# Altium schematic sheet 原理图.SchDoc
size A2
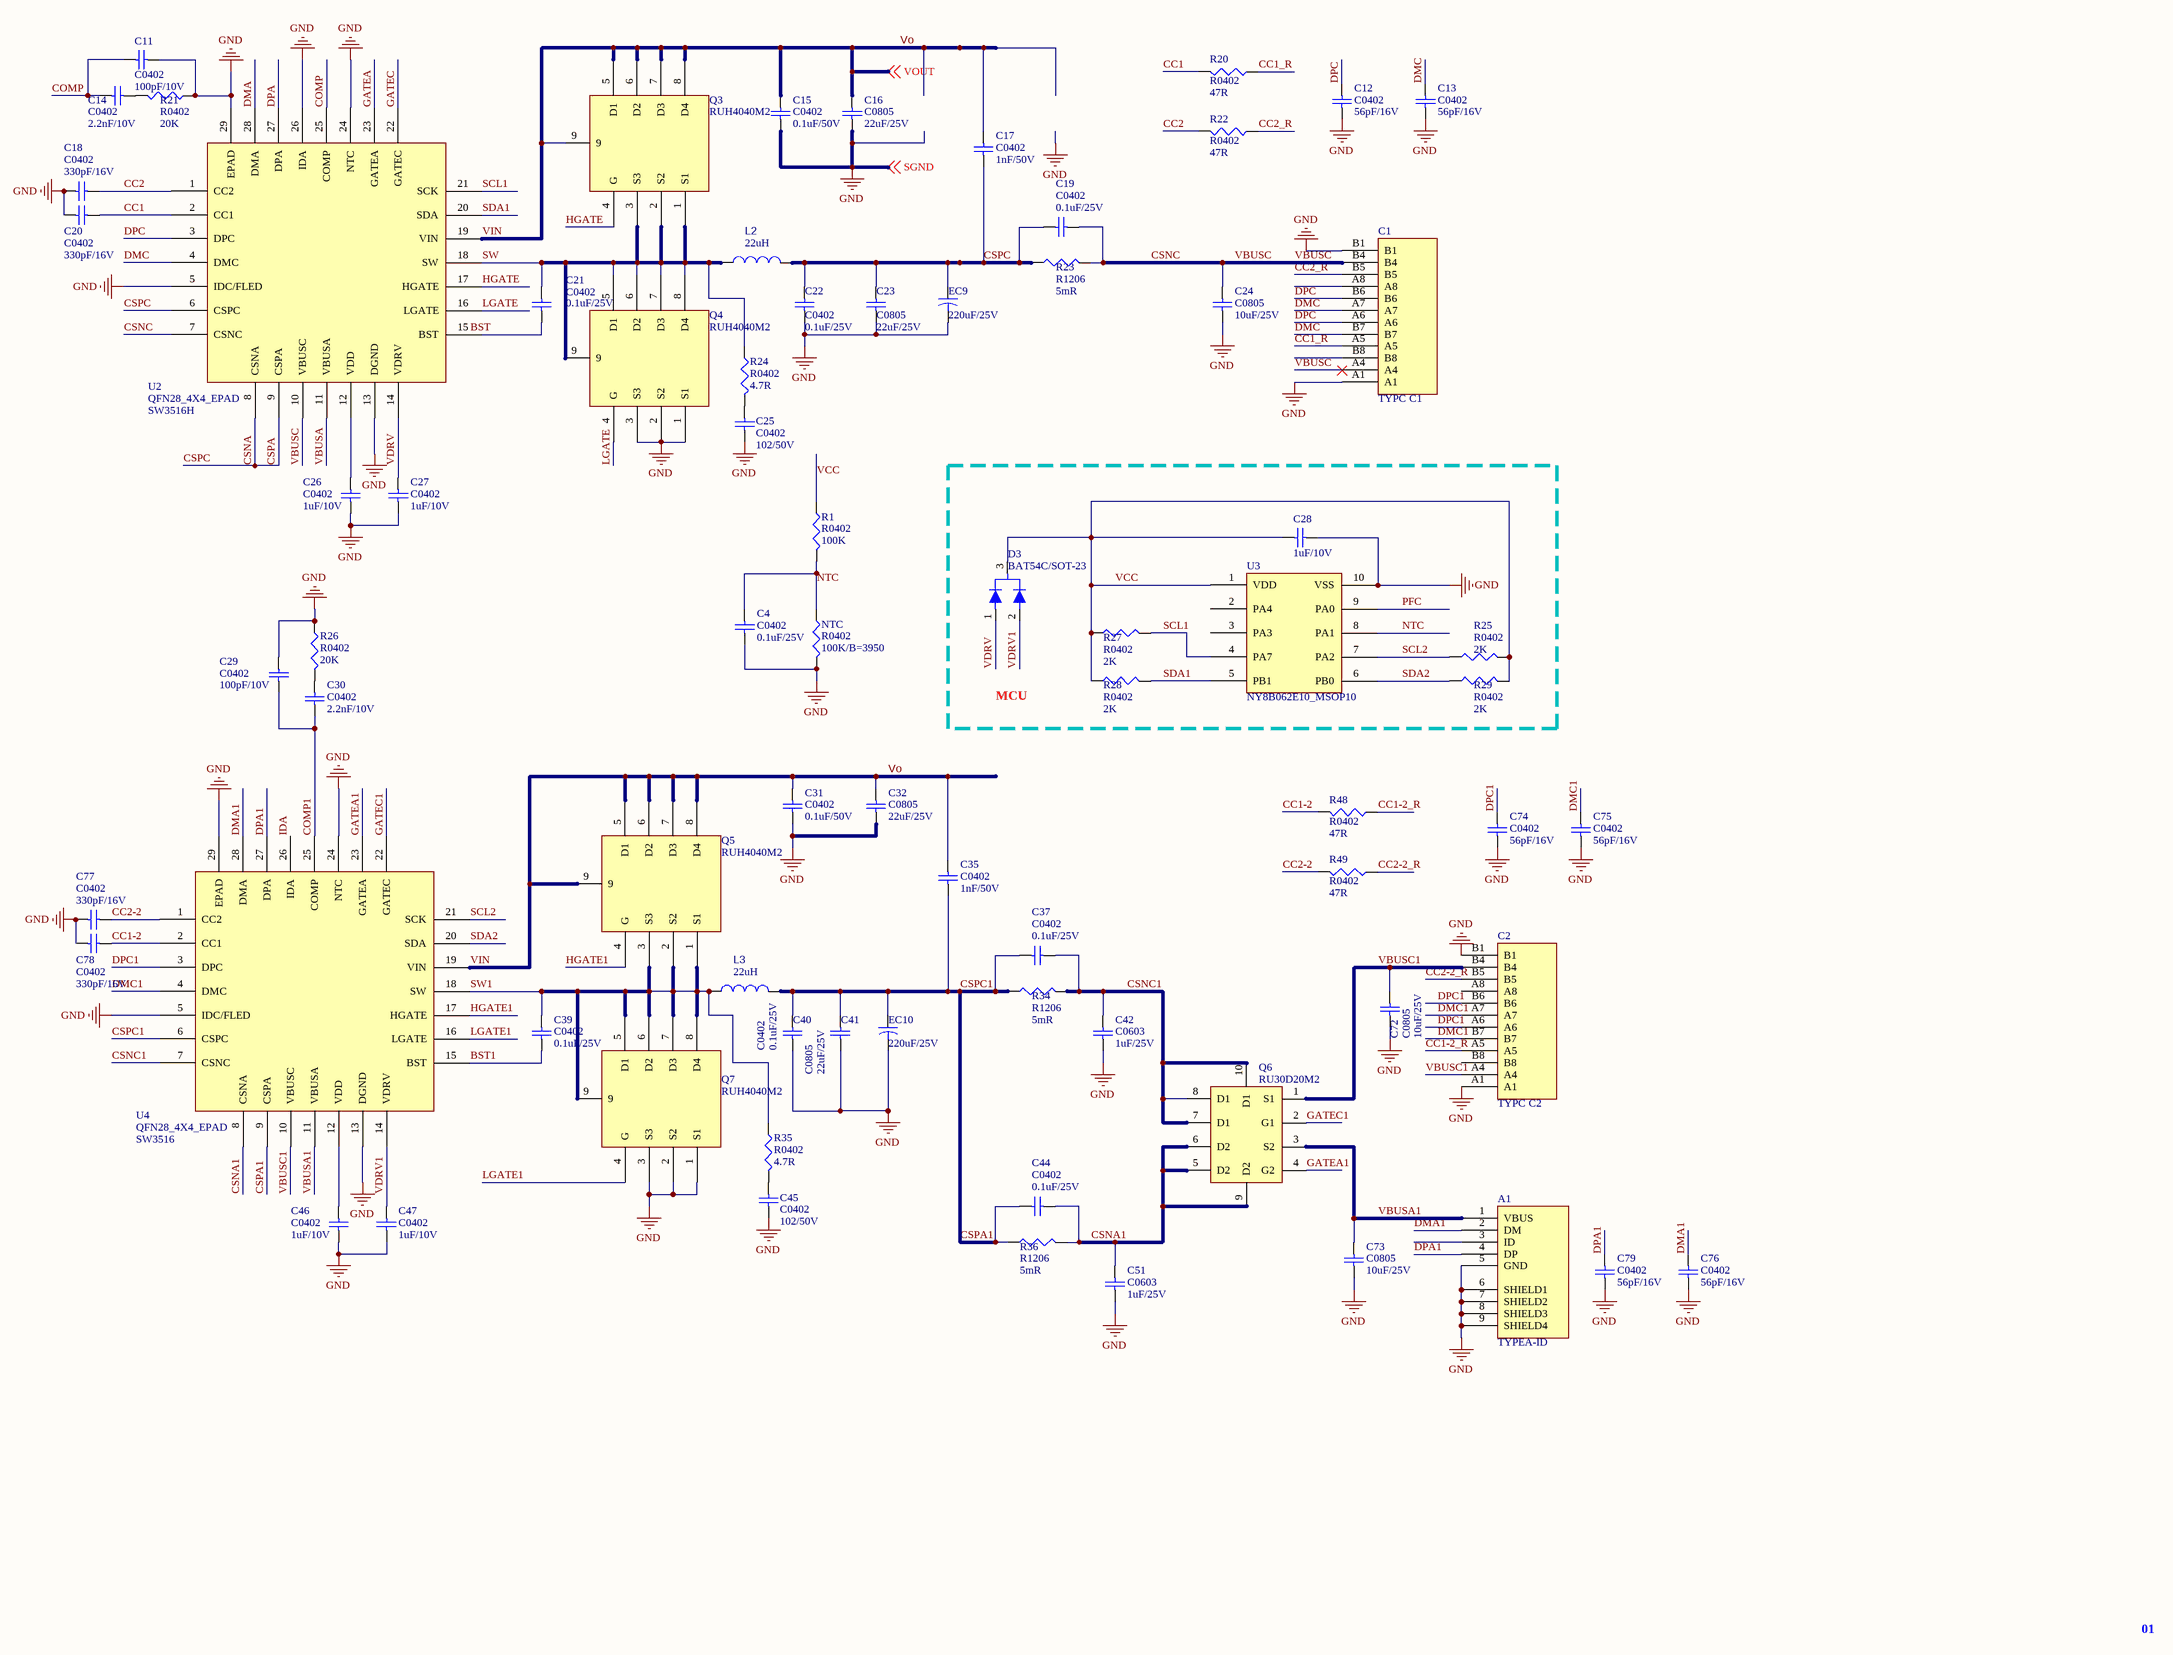
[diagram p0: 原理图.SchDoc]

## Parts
A1  TYPEA-ID  [TYPEA-VOOC]
C1  TYPC C1  [USB C1]
C2  TYPC C2  [USB C1]
C4  C0402  value 0.1uF/25V  [0402C]
C11  C0402  value 100pF/10V  [0402C]
C12  C0402  value 56pF/16V  [0402C]
C13  C0402  value 56pF/16V  [0402C]
C14  C0402  value 2.2nF/10V  [0402C]
C15  C0402  value 0.1uF/50V  [0402C]
C16  C0805  value 22uF/25V  [0805C]
C17  C0402  value 1nF/50V  [0402C]
C18  C0402  value 330pF/16V  [0402C]
C19  C0402  value 0.1uF/25V  [0402C]
C20  C0402  value 330pF/16V  [0402C]
C21  C0402  value 0.1uF/25V  [0402C]
C22  C0402  value 0.1uF/25V  [0402C]
C23  C0805  value 22uF/25V  [0805C]
C24  C0805  value 10uF/25V  [0805C]
C25  C0402  value 102/50V  [0603C]
C26  C0402  value 1uF/10V  [0402C]
C27  C0402  value 1uF/10V  [0402C]
C28  value 1uF/10V  [0402C]  (hidden comment: Cap)
C29  C0402  value 100pF/10V  [0402C]
C30  C0402  value 2.2nF/10V  [0402C]
C31  C0402  value 0.1uF/50V  [0402C]
C32  C0805  value 22uF/25V  [0805C]
C35  C0402  value 1nF/50V  [0402C]
C37  C0402  value 0.1uF/25V  [0402C]
C39  C0402  value 0.1uF/25V  [0402C]
C40  C0402  value 0.1uF/25V  [0402C]
C41  C0805  value 22uF/25V  [0805C]
C42  C0603  value 1uF/25V  [0603C]
C44  C0402  value 0.1uF/25V  [0402C]
C45  C0402  value 102/50V  [0603C]
C46  C0402  value 1uF/10V  [0402C]
C47  C0402  value 1uF/10V  [0402C]
C51  C0603  value 1uF/25V  [0603C]
C72  C0805  value 10uF/25V  [0805C]
C73  C0805  value 10uF/25V  [0805C]
C74  C0402  value 56pF/16V  [0402C]
C75  C0402  value 56pF/16V  [0402C]
C76  C0402  value 56pF/16V  [0402C]
C77  C0402  value 330pF/16V  [0402C]
C78  C0402  value 330pF/16V  [0402C]
C79  C0402  value 56pF/16V  [0402C]
D3  BAT54C/SOT-23  [SOT-23]
EC9  value 220uF/25V  [C6*12]  (hidden comment: Cap_Pol)
EC10  value 220uF/25V  [EC-5*10]  (hidden comment: Cap_Pol)
L2  value 22uH  [L11.5X5.5]  (hidden comment: R0603)
L3  value 22uH  [L11.5X5.5]  (hidden comment: R0603)
NTC  R0402  value 100K/B=3950  [0603]
Q3  RUH4040M2  [DFN3*3-EPAD - duplicate]
Q4  RUH4040M2  [DFN3*3-EPAD - duplicate]
Q5  RUH4040M2  [DFN3*3-EPAD - duplicate]
Q6  RU30D20M2  [DUAL-DFN3333]
Q7  RUH4040M2  [DFN3*3-EPAD - duplicate]
R1  R0402  value 100K  [0603]
R20  R0402  value 47R  [0603]
R21  R0402  value 20K  [R0402]
R22  R0402  value 47R  [0603]
R23  R1206  value 5mR  [1206]
R24  R0402  value 4.7R  [0603]
R25  R0402  value 2K  [R0402]
R26  R0402  value 20K  [R0402]
R27  R0402  value 2K  [R0402]
R28  R0402  value 2K  [R0402]
R29  R0402  value 2K  [R0402]
R34  R1206  value 5mR  [1206]
R35  R0402  value 4.7R  [0603]
R36  R1206  value 5mR  [1206]
R48  R0402  value 47R  [0603]
R49  R0402  value 47R  [0603]
U2  SW3516H  Footprint: QFN28_4X4_EPAD  [QFN28-4*4mm]
U3  NY8B062E10_MSOP10  [MSOP10]
U4  SW3516  Footprint: QFN28_4X4_EPAD  [QFN28-4*4mm]

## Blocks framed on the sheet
MCU: C28 D3 R25 R27-R29 U3

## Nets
GND: A1.5(GND) A1.6(SHIELD1) A1.7(SHIELD2) A1.8(SHIELD3) A1.9(SHIELD4) C1.A1 C1.B1 C2.A1 C2.B1 C4.1 C11.2 C12.1 C13.1 C15.1 C16.1 C18.2 C20.2 C22.1 C23.1 C24.1 C25.2 C26.1 C27.1 C28.2 C29.2 C31.1 C32.1 C40.1 C41.1 C42.1 C45.2 C46.1 C47.1 C51.1 C72.1 C73.1 C74.1 C75.1 C76.1 C77.2 C78.2 C79.1 EC9.2 EC10.2 NTC.2 Q4.1(S1) Q4.2(S2) Q4.3(S3) Q7.1(S1) Q7.2(S2) Q7.3(S3) R21.1 R26.1 U2.5(IDC/FLED) U2.13(DGND) U2.24(NTC) U2.26(IDA) U2.29(EPAD) U3.10(VSS) U4.5(IDC/FLED) U4.13(DGND) U4.24(NTC) U4.29(EPAD) ; off-sheet SGND  [also labelled SGND]
BST1: C39.1 U4.15(BST)
CC1: C20.1 R20.2 U2.2(CC1)
CC1-2: C78.1 R48.2 U4.2(CC1)
CC1-2_R: C2.A5 R48.1
CC1_R: C1.A5 R20.1
CC2: C18.1 R22.2 U2.1(CC2)
CC2-2: C77.1 R49.2 U4.1(CC2)
CC2-2_R: C2.B5 R49.1
CC2_R: C1.B5 R22.1
COMP: C11.1 C14.1 U2.25(COMP)
COMP1: C29.1 C30.1 U4.25(COMP)
CSNA: C17.1 C19.2 C22.2 C23.2 EC9.1 L2.2 R23.1 U2.6(CSPC) U2.8(CSNA) U2.9(CSPA)  [also labelled CSPA, CSPC]
CSNA1: C44.1 C51.2 Q6.5(D2) Q6.6(D2) Q6.9(D2) R36.2 U4.8(CSNA)
CSNC: C1.A4 C1.B4 C19.1 C24.2 R23.2 U2.7(CSNC) U2.10(VBUSC)  [also labelled VBUSC]
CSNC1: C37.1 C42.2 Q6.7(D1) Q6.8(D1) Q6.10(D1) R34.2 U4.7(CSNC)
CSPA1: C35.1 C37.2 C40.2 C41.2 C44.2 EC10.1 L3.2 R34.1 R36.1 U4.6(CSPC) U4.9(CSPA)  [also labelled CSPC1]
DMA: U2.28(DMA)
DMA1: A1.2(DM) C76.2 U4.28(DMA)
DMC: C1.A7 C1.B7 C13.2 U2.4(DMC)
DMC1: C2.A7 C2.B7 C75.2 U4.4(DMC)
DPA: U2.27(DPA)
DPA1: A1.4(DP) C79.2 U4.27(DPA)
DPC: C1.A6 C1.B6 C12.2 U2.3(DPC)
DPC1: C2.A6 C2.B6 C74.2 U4.3(DPC)
GATEA: U2.23(GATEA)
GATEA1: Q6.4(G2) U4.23(GATEA)
GATEC: U2.22(GATEC)
GATEC1: Q6.2(G1) U4.22(GATEC)
HGATE: Q3.4(G) U2.17(HGATE)
HGATE1: Q5.4(G) U4.17(HGATE)
IDA: U4.26(IDA)
LGATE: Q4.4(G) U2.16(LGATE)
LGATE1: Q7.4(G) U4.16(LGATE)
NTC: C4.2 NTC.1 R1.2 U3.8(PA1)
PFC: U3.9(PA0)
SCL1: R27.2 U2.21(SCK) U3.4(PA7)
SCL2: R25.1 U3.7(PA2) U4.21(SCK)
SDA1: R28.2 U2.20(SDA) U3.5(PB1)
SDA2: R29.1 U3.6(PB0) U4.20(SDA)
SW: C21.2 L2.1 Q3.1(S1) Q3.2(S2) Q3.3(S3) Q4.5(D1) Q4.6(D2) Q4.7(D3) Q4.8(D4) Q4.9 R24.1 U2.18(SW)
SW1: C39.2 L3.1 Q5.1(S1) Q5.2(S2) Q5.3(S3) Q7.5(D1) Q7.6(D2) Q7.7(D3) Q7.8(D4) Q7.9 R35.1 U4.18(SW)
VBUSA: U2.11(VBUSA)
VBUSA1: A1.1(VBUS) C73.2 Q6.3(S2) U4.11(VBUSA)
VBUSC1: C2.A4 C2.B4 C72.2 Q6.1(S1) U4.10(VBUSC)
VCC: C28.1 D3.3 R1.1 R25.2 R27.1 R28.1 R29.2 U3.1(VDD)
VDRV: C27.2 D3.1 U2.14(VDRV)
VDRV1: C47.2 D3.2 U4.14(VDRV)
VIN: C15.2 C16.2 C17.2 C31.2 C32.2 C35.2 Q3.5(D1) Q3.6(D2) Q3.7(D3) Q3.8(D4) Q3.9 Q5.5(D1) Q5.6(D2) Q5.7(D3) Q5.8(D4) Q5.9 U2.19(VIN) U4.19(VIN) ; off-sheet VOUT  [also labelled Vo, VOUT]
NetC14_2: C14.2 R21.2
NetC21_1: C21.1 U2.15(BST)
NetC25_1: C25.1 R24.2
NetC26_2: C26.2 U2.12(VDD)
NetC30_2: C30.2 R26.2
NetC45_1: C45.1 R35.2
NetC46_2: C46.2 U4.12(VDD)

Not connected (* = marked no-connect by the designer): A1 3(ID); C1 A8 B8; C2 A8 B8; U3 2(PA4) 3(PA3)

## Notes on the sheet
- 01
- Labels drawn without touching a wire or pin: BST

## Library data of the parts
C1 C2 = TYPC C
C4 C11 C14-C23 C25-C27 C29-C32 C35 C37 C39-C41 C44-C47 C77 C78 = CAP0603: Capacitor
C12 C13 C24 C42 C51 C72-C76 C79 = CAP0805: Capacitor
C28 = Cap: Capacitor
D3 = D3
EC9 EC10 = Cap_Pol: Capacitor
L2 L3 = INDUCTOR
NTC R1 R20-R29 R34-R36 R48 R49 = RES: Resistor
Q3-Q5 Q7 = DFN3333
Q6 = DUL NMOS
U2 U4 = SW3517
U3 = 153_MSOP10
